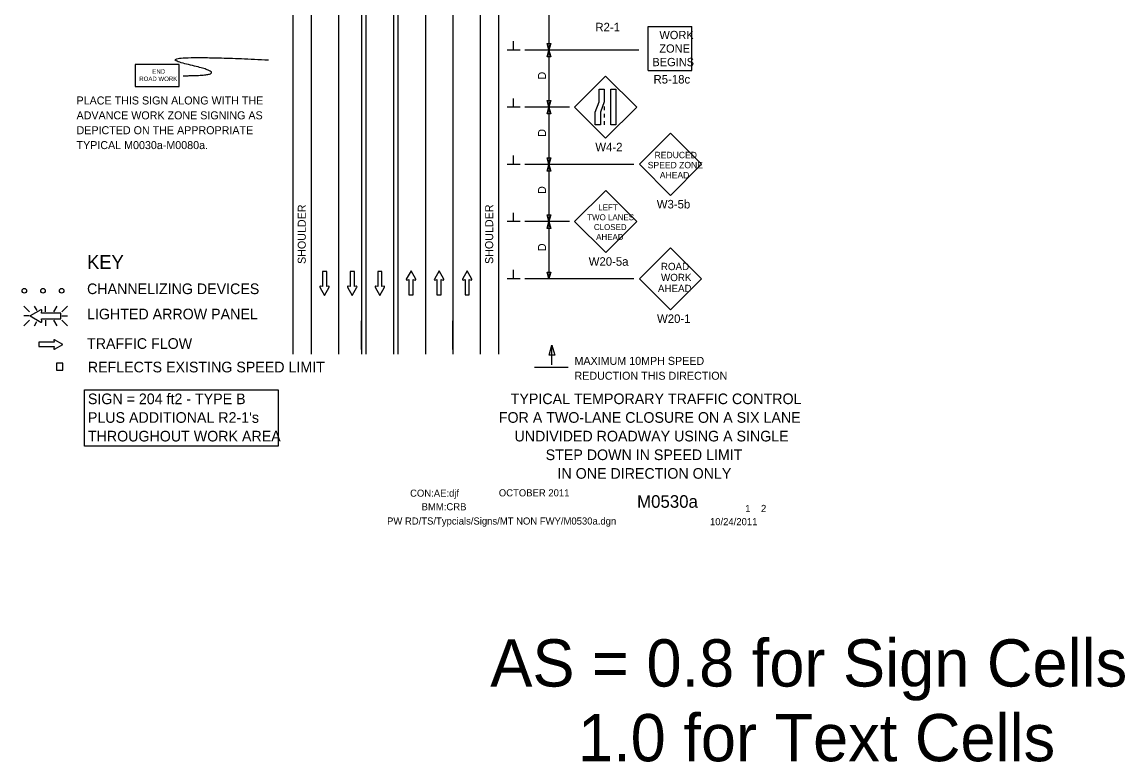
# Model space of a CAD drawing. Extents: x 16751 to 18475, y 5726 to 6923.
# Drawn here: x 16751 to 17716, y 5726 to 6373 of the extents above; entities that cross this region are included whole.
import ezdxf

# ---------------------------------------------------------------- set-up
doc = ezdxf.new("R2010")
doc.units = 0
for name, color, linetype in [('ALI_LEGAL_EX', 7, 'Continuous'), ('BORDER', 7, 'Continuous'), ('BORDER_SIGNAL_WO', 7, 'Continuous'), ('MT_SCRATCH_LEVEL_E', 7, 'Continuous'), ('PAVT_EDGE_EX', 7, 'Continuous'), ('TRAFFIC_SIGNS_PR', 7, 'Continuous'), ('TYPICAL_TEXT_DIMEN_EX', 7, 'Continuous'), ('TYPICAL_TEXT_DIMEN_PR', 7, 'Continuous')]:
    doc.layers.add(name, color=color, linetype=linetype)

msp = doc.modelspace()

# ---------------------------------------------------------------- linework, layer by layer
at = {"layer": 'ALI_LEGAL_EX'}
for p, q in [((17028.08, 6911.72), (17028.08, 6082.53)), ((17048.08, 6911.72), (17048.08, 6082.53)), ((17052.08, 6911.72), (17052.08, 6082.53)), ((17104.08, 6911.72), (17104.08, 6082.53)), ((17128.08, 6911.72), (17128.08, 6082.53)), ((17128.08, 6911.72), (17128.08, 6082.53))]:
    msp.add_line(p, q, dxfattribs=at)
for points in [[(17028.08, 6311.72), (17028.08, 6286.72)], [(17052.08, 6311.72), (17052.08, 6286.72)], [(17104.08, 6311.72), (17104.08, 6286.72)], [(17128.08, 6311.72), (17128.08, 6286.72)], [(17028.08, 6211.72), (17028.08, 6186.72)], [(17052.08, 6211.72), (17052.08, 6186.72)], [(17104.08, 6211.72), (17104.08, 6186.72)], [(17128.08, 6211.72), (17128.08, 6186.72)], [(17028.08, 6111.72), (17028.08, 6086.72)], [(17048.08, 6086.72), (17048.08, 6111.72)], [(17052.08, 6111.72), (17052.08, 6086.72)], [(17104.08, 6111.72), (17104.08, 6086.72)], [(17128.08, 6086.72), (17128.08, 6111.72)], [(17128.08, 6111.72), (17128.08, 6086.72)]]:
    msp.add_lwpolyline(points, dxfattribs=at)
at = {"layer": 'MT_SCRATCH_LEVEL_E'}
for p, q in [((17017.74, 6154.9), (17014, 6154.9)), ((17014, 6154.9), (17014, 6141.64)), ((17017.74, 6154.9), (17014, 6154.9)), ((17014, 6154.9), (17014, 6141.64)), ((17017.74, 6141.64), (17017.74, 6154.9)), ((17017.74, 6141.64), (17017.74, 6154.9)), ((17042, 6154.9), (17038.26, 6154.9)), ((17038.26, 6154.9), (17038.26, 6141.64)), ((17042, 6154.9), (17038.26, 6154.9)), ((17038.26, 6154.9), (17038.26, 6141.64)), ((17042, 6141.64), (17042, 6154.9)), ((17042, 6141.64), (17042, 6154.9)), ((17066.1, 6154.9), (17062.36, 6154.9)), ((17062.36, 6154.9), (17062.36, 6141.64)), ((17066.1, 6154.9), (17062.36, 6154.9)), ((17062.36, 6154.9), (17062.36, 6141.64)), ((17066.1, 6141.64), (17066.1, 6154.9)), ((17066.1, 6141.64), (17066.1, 6154.9)), ((17091.51, 6155.36), (17087.4, 6148.12)), ((17091.51, 6155.36), (17087.4, 6148.12)), ((17095.66, 6148.12), (17091.51, 6155.36)), ((17095.66, 6148.12), (17091.51, 6155.36)), ((17116.04, 6155.36), (17111.93, 6148.12)), ((17116.04, 6155.36), (17111.93, 6148.12)), ((17120.19, 6148.12), (17116.04, 6155.36)), ((17120.19, 6148.12), (17116.04, 6155.36)), ((17140.6, 6155.36), (17136.49, 6148.12)), ((17140.6, 6155.36), (17136.49, 6148.12)), ((17144.75, 6148.12), (17140.6, 6155.36)), ((17144.75, 6148.12), (17140.6, 6155.36)), ((17087.89, 6147.43), (17089.66, 6147.75)), ((17087.89, 6147.43), (17089.66, 6147.75)), ((17089.66, 6147.75), (17089.66, 6134.49)), ((17089.66, 6147.75), (17089.66, 6134.49)), ((17093.4, 6134.49), (17093.4, 6147.75)), ((17093.4, 6147.75), (17095.18, 6147.43)), ((17093.4, 6134.49), (17093.4, 6147.75)), ((17093.4, 6147.75), (17095.18, 6147.43)), ((17112.41, 6147.43), (17114.19, 6147.75)), ((17112.41, 6147.43), (17114.19, 6147.75)), ((17114.19, 6147.75), (17114.19, 6134.49)), ((17114.19, 6147.75), (17114.19, 6134.49)), ((17117.93, 6134.49), (17117.93, 6147.75)), ((17117.93, 6147.75), (17119.71, 6147.43)), ((17117.93, 6134.49), (17117.93, 6147.75)), ((17117.93, 6147.75), (17119.71, 6147.43)), ((17136.97, 6147.43), (17138.75, 6147.75)), ((17136.97, 6147.43), (17138.75, 6147.75)), ((17138.75, 6147.75), (17138.75, 6134.49)), ((17138.75, 6147.75), (17138.75, 6134.49)), ((17142.49, 6134.49), (17142.49, 6147.75)), ((17142.49, 6147.75), (17144.27, 6147.43)), ((17142.49, 6134.49), (17142.49, 6147.75)), ((17142.49, 6147.75), (17144.27, 6147.43)), ((17011.75, 6141.27), (17015.89, 6134.03)), ((17011.75, 6141.27), (17015.89, 6134.03)), ((17014, 6141.64), (17012.23, 6141.96)), ((17014, 6141.64), (17012.23, 6141.96)), ((17015.89, 6134.03), (17020, 6141.27)), ((17015.89, 6134.03), (17020, 6141.27)), ((17019.52, 6141.96), (17017.74, 6141.64)), ((17019.52, 6141.96), (17017.74, 6141.64)), ((17036, 6141.27), (17040.15, 6134.03)), ((17036, 6141.27), (17040.15, 6134.03)), ((17038.26, 6141.64), (17036.48, 6141.96)), ((17038.26, 6141.64), (17036.48, 6141.96)), ((17040.15, 6134.03), (17044.26, 6141.27)), ((17040.15, 6134.03), (17044.26, 6141.27)), ((17043.78, 6141.96), (17042, 6141.64)), ((17043.78, 6141.96), (17042, 6141.64)), ((17060.1, 6141.27), (17064.25, 6134.03)), ((17060.1, 6141.27), (17064.25, 6134.03)), ((17062.36, 6141.64), (17060.58, 6141.96)), ((17062.36, 6141.64), (17060.58, 6141.96)), ((17064.25, 6134.03), (17068.36, 6141.27)), ((17064.25, 6134.03), (17068.36, 6141.27)), ((17067.88, 6141.96), (17066.1, 6141.64)), ((17067.88, 6141.96), (17066.1, 6141.64)), ((17089.66, 6134.49), (17093.4, 6134.49)), ((17089.66, 6134.49), (17093.4, 6134.49)), ((17114.19, 6134.49), (17117.93, 6134.49)), ((17114.19, 6134.49), (17117.93, 6134.49)), ((17138.75, 6134.49), (17142.49, 6134.49)), ((17138.75, 6134.49), (17142.49, 6134.49)), ((16779.38, 6092.98), (16766.12, 6092.98)), ((16766.12, 6092.98), (16766.12, 6089.24)), ((16779.38, 6092.98), (16766.12, 6092.98)), ((16766.12, 6092.98), (16766.12, 6089.24)), ((16766.12, 6089.24), (16779.38, 6089.24)), ((16766.12, 6089.24), (16779.38, 6089.24)), ((16779.06, 6094.76), (16779.38, 6092.98)), ((16779.06, 6094.76), (16779.38, 6092.98)), ((16779.38, 6089.24), (16779.06, 6087.47)), ((16779.38, 6089.24), (16779.06, 6087.47)), ((16786.99, 6091.13), (16779.74, 6095.24)), ((16786.99, 6091.13), (16779.74, 6095.24)), ((16779.74, 6086.99), (16786.99, 6091.13)), ((16779.74, 6086.99), (16786.99, 6091.13))]:
    msp.add_line(p, q, dxfattribs=at)
for centre, start, end in [((17087.81, 6147.89), 150.42484, 279.96381), ((17087.81, 6147.89), 150.42484, 279.96381), ((17095.25, 6147.89), 260.03619, 29.77312), ((17095.25, 6147.89), 260.03619, 29.77312), ((17112.34, 6147.89), 150.42484, 279.96381), ((17112.34, 6147.89), 150.42484, 279.96381), ((17119.78, 6147.89), 260.03619, 29.77312), ((17119.78, 6147.89), 260.03619, 29.77312), ((17136.9, 6147.89), 150.42484, 279.96381), ((17136.9, 6147.89), 150.42484, 279.96381), ((17144.34, 6147.89), 260.03619, 29.77312), ((17144.34, 6147.89), 260.03619, 29.77312), ((17012.16, 6141.5), 80.03619, 209.77312), ((17012.16, 6141.5), 80.03619, 209.77312), ((17019.6, 6141.5), 330.42484, 99.96381), ((17019.6, 6141.5), 330.42484, 99.96381), ((17036.41, 6141.5), 80.03619, 209.77312), ((17036.41, 6141.5), 80.03619, 209.77312), ((17043.85, 6141.5), 330.42484, 99.96381), ((17043.85, 6141.5), 330.42484, 99.96381), ((17060.51, 6141.5), 80.03619, 209.77312), ((17060.51, 6141.5), 80.03619, 209.77312), ((17067.96, 6141.5), 330.42484, 99.96381), ((17067.96, 6141.5), 330.42484, 99.96381), ((16779.52, 6094.84), 60.42484, 189.96381), ((16779.52, 6094.84), 60.42484, 189.96381), ((16779.52, 6087.4), 170.03619, 299.77312), ((16779.52, 6087.4), 170.03619, 299.77312)]:
    msp.add_arc(centre, 0.463, start, end, dxfattribs=at)
at = {"layer": 'PAVT_EDGE_EX'}
for p, q in [((16988.08, 6911.72), (16988.08, 6082.53)), ((17004.08, 6911.72), (17004.08, 6082.53)), ((17076.08, 6911.72), (17076.08, 6082.53)), ((17080.08, 6911.72), (17080.08, 6082.53)), ((17152.08, 6911.72), (17152.08, 6082.53)), ((17168.08, 6911.72), (17168.08, 6082.53))]:
    msp.add_line(p, q, dxfattribs=at)
at = {"layer": 'TRAFFIC_SIGNS_PR'}
for p, q in [((17298.75, 6330.61), (17298.75, 6369.01)), ((17298.75, 6369.01), (17337.15, 6369.01)), ((17337.15, 6330.61), (17337.15, 6369.01)), ((17298.75, 6330.61), (17337.15, 6330.61)), ((17261.72, 6325.68), (17234.57, 6298.53)), ((17288.87, 6298.53), (17261.72, 6325.68)), ((17234.57, 6298.53), (17261.72, 6271.38)), ((17260.47, 6299.02), (17260.47, 6295.82)), ((17261.72, 6271.38), (17288.87, 6298.53)), ((17260.47, 6292.62), (17260.47, 6289.42)), ((17260.47, 6286.22), (17260.47, 6283.02)), ((17318.46, 6275.75), (17291.3, 6248.59)), ((17345.61, 6248.59), (17318.46, 6275.75)), ((17291.3, 6248.59), (17318.46, 6221.44)), ((17318.46, 6221.44), (17345.61, 6248.59)), ((17261.73, 6225.66), (17234.58, 6198.51)), ((17288.88, 6198.51), (17261.73, 6225.66)), ((17234.58, 6198.51), (17261.73, 6171.36)), ((17261.73, 6171.36), (17288.88, 6198.51)), ((17318.46, 6175.69), (17291.31, 6148.54)), ((17345.61, 6148.54), (17318.46, 6175.69)), ((17291.31, 6148.54), (17318.46, 6121.39)), ((17318.46, 6121.39), (17345.61, 6148.54)), ((16752.8, 6124.52), (16757.73, 6119.59)), ((16764.56, 6120.7), (16762.35, 6124.52)), ((16771.88, 6119.59), (16771.88, 6124.52)), ((16779.12, 6119.59), (16781.96, 6124.52)), ((16786.03, 6119.59), (16790.97, 6124.52)), ((16757.73, 6116.03), (16752.8, 6116.03)), ((16786.03, 6116.03), (16790.97, 6116.03)), ((16752.8, 6107.54), (16757.73, 6112.47)), ((16762.31, 6107.54), (16764.42, 6111.2)), ((16771.88, 6112.47), (16771.88, 6107.54)), ((16782.01, 6107.54), (16779.16, 6112.47)), ((16786.03, 6112.47), (16790.97, 6107.54))]:
    msp.add_line(p, q, dxfattribs=at)
for points in [[(16850.28, 6316.64), (16888.68, 6316.64), (16888.68, 6335.84), (16850.28, 6335.84)], [(17260.47, 6314.27), (17260.47, 6303.09), (17257.13, 6294.2), (17257.13, 6283.02), (17252.63, 6283.02), (17252.63, 6294.2), (17255.98, 6303.09), (17255.98, 6314.27)], [(17270.61, 6314.27), (17270.61, 6283.02), (17266.12, 6283.02), (17266.12, 6314.27)], [(16781.55, 6068.55), (16787.14, 6068.55), (16787.14, 6074.73), (16781.55, 6074.73)]]:
    msp.add_lwpolyline(points, close=True, dxfattribs=at)
for points in [[(16767.81, 6121.31), (16758.52, 6116.03), (16767.81, 6110.71)], [(16768.68, 6111.34), (16768.28, 6113.6), (16785.3, 6113.6), (16785.3, 6118.4), (16768.28, 6118.4), (16768.69, 6120.69)]]:
    msp.add_lwpolyline(points, dxfattribs=at)
for centre in [(16753.36, 6138.06), (16769.66, 6138.06), (16785.96, 6138.06)]:
    msp.add_circle(centre, 2, dxfattribs=at)
for centre, radius, start, end in [((16768.1, 6120.78), 0.598, 350.73078, 118.89165), ((16768.09, 6111.23), 0.597, 241.48329, 9.95933)]:
    msp.add_arc(centre, radius, start, end, dxfattribs=at)
msp.add_open_spline([(16892.27, 6326.02), (16939.51, 6326.02), (16854.48, 6345.37), (16966.78, 6339.88)], degree=2, dxfattribs=at)
at = {"layer": 'TYPICAL_TEXT_DIMEN_EX'}
msp.add_lwpolyline([(16805.94, 6051.34), (16975.39, 6051.34), (16975.39, 6002.14), (16805.94, 6002.14)], close=True, dxfattribs=at)
at = {"layer": 'TYPICAL_TEXT_DIMEN_PR'}
for p, q in [((17212.08, 6398.45), (17212.08, 6348.45)), ((17181.2, 6348.45), (17181.2, 6356.23)), ((17186.83, 6348.45), (17175.58, 6348.45)), ((17290.63, 6348.45), (17191.08, 6348.45)), ((17212.08, 6348.45), (17210.51, 6354.31)), ((17210.51, 6354.31), (17212.08, 6354.31)), ((17210.51, 6342.59), (17212.08, 6348.45)), ((17212.08, 6354.31), (17213.65, 6354.31)), ((17213.65, 6354.31), (17212.08, 6348.45)), ((17212.08, 6348.45), (17213.65, 6342.59)), ((17212.08, 6348.45), (17212.08, 6298.45)), ((17212.08, 6342.59), (17210.51, 6342.59)), ((17213.65, 6342.59), (17212.08, 6342.59)), ((17186.83, 6298.45), (17175.58, 6298.45)), ((17181.2, 6298.45), (17181.2, 6306.23)), ((17230.08, 6298.45), (17191.08, 6298.45)), ((17212.08, 6298.45), (17210.51, 6304.31)), ((17210.51, 6304.31), (17212.08, 6304.31)), ((17210.51, 6292.59), (17212.08, 6298.45)), ((17212.08, 6304.31), (17213.65, 6304.31)), ((17213.65, 6304.31), (17212.08, 6298.45)), ((17212.08, 6298.45), (17212.08, 6248.45)), ((17212.08, 6298.45), (17213.65, 6292.59)), ((17212.08, 6292.59), (17210.51, 6292.59)), ((17213.65, 6292.59), (17212.08, 6292.59)), ((17181.2, 6248.45), (17181.2, 6256.23)), ((17212.08, 6248.45), (17210.51, 6254.31)), ((17210.51, 6254.31), (17212.08, 6254.31)), ((17212.08, 6254.31), (17213.65, 6254.31)), ((17213.65, 6254.31), (17212.08, 6248.45)), ((17186.83, 6248.45), (17175.58, 6248.45)), ((17286.28, 6248.45), (17191.08, 6248.45)), ((17210.51, 6242.59), (17212.08, 6248.45)), ((17212.08, 6242.59), (17210.51, 6242.59)), ((17212.08, 6248.45), (17212.08, 6198.45)), ((17212.08, 6248.45), (17213.65, 6242.59)), ((17213.65, 6242.59), (17212.08, 6242.59)), ((17181.2, 6198.45), (17181.2, 6206.23)), ((17212.08, 6198.45), (17210.51, 6204.31)), ((17210.51, 6204.31), (17212.08, 6204.31)), ((17212.08, 6204.31), (17213.65, 6204.31)), ((17213.65, 6204.31), (17212.08, 6198.45)), ((17186.83, 6198.45), (17175.58, 6198.45)), ((17230.08, 6198.45), (17191.08, 6198.45)), ((17210.51, 6192.59), (17212.08, 6198.45)), ((17212.08, 6192.59), (17210.51, 6192.59)), ((17212.08, 6198.45), (17212.08, 6148.45)), ((17212.08, 6198.45), (17213.65, 6192.59)), ((17213.65, 6192.59), (17212.08, 6192.59)), ((17181.2, 6148.45), (17181.2, 6156.23)), ((17212.08, 6148.45), (17210.51, 6154.31)), ((17210.51, 6154.31), (17212.08, 6154.31)), ((17212.08, 6154.31), (17213.65, 6154.31)), ((17213.65, 6154.31), (17212.08, 6148.45)), ((17186.83, 6148.45), (17175.58, 6148.45)), ((17286.28, 6148.45), (17191.08, 6148.45)), ((17212.42, 6081.69), (17214.78, 6090.49)), ((17214.78, 6073.36), (17214.78, 6090.49)), ((17214.78, 6090.49), (17217.13, 6081.69)), ((17214.78, 6081.69), (17212.42, 6081.69)), ((17217.13, 6081.69), (17214.78, 6081.69)), ((17228.95, 6070.86), (17199.51, 6070.86))]:
    msp.add_line(p, q, dxfattribs=at)

# ---------------------------------------------------------------- texts
at = {"layer": 'BORDER'}
for s, p in [('TYPICAL TEMPORARY TRAFFIC CONTROL', (17178.7, 6038.95)), ('FOR A TWO-LANE CLOSURE ON A SIX LANE', (17168.28, 6022.65)), ('UNDIVIDED ROADWAY USING A SINGLE', (17181.98, 6006.35)), ('STEP DOWN IN SPEED LIMIT', (17209.26, 5990.05)), ('IN ONE DIRECTION ONLY', (17219.61, 5973.75))]:
    msp.add_text(s, height=9.3, dxfattribs=at).set_placement(p)
at = {"layer": 'BORDER_SIGNAL_WO'}
for s, height, p in [('CON:AE:djf', 6.2, (17090.69, 5958.06)), ('    OCTOBER 2011    ', 6.2, (17159.08, 5958.34)), ('BMM:CRB   ', 6.2, (17100.81, 5946.17)), ('    M0530a   ', 11, (17272.86, 5948.38)), (' 1    2 ', 6.2, (17381.45, 5944.7)), ('PW RD/TS/Typcials/Signs/MT NON FWY/M0530a.dgn    ', 6.2, (17070.55, 5933.71)), ('10/24/2011    ', 6.2, (17352.93, 5933.13)), ('AS = 0.8 for Sign Cells', 41.2877, (17160.83, 5792.11)), ('     1.0 for Text Cells', 41.2877, (17160.83, 5726.82))]:
    msp.add_text(s, height=height, dxfattribs=at).set_placement(p)
at = {"layer": 'TRAFFIC_SIGNS_PR'}
for s, height, p in [('R2-1', 7.44, (17252.7, 6364.81)), ('WORK', 7.217, (17308.74, 6357.97)), ('ZONE', 7.217, (17308.63, 6346.16)), ('BEGINS', 7.217, (17302.55, 6334.35)), ('END', 3.831, (16865.28, 6327.78)), ('ROAD WORK', 3.831, (16853.89, 6321.39)), ('R5-18c', 7.44, (17303.56, 6319.17)), ('PLACE THIS SIGN ALONG WITH THE', 7, (16799, 6300.87)), ('ADVANCE WORK ZONE SIGNING AS', 7, (16799, 6287.87)), ('DEPICTED ON THE APPROPRIATE', 7, (16799, 6274.87)), ('TYPICAL M0030a-M0080a.', 7, (16799, 6261.87)), ('W4-2', 7.44, (17252.68, 6259.94)), ('REDUCED', 5.6, (17304.51, 6253.9)), ('SPEED ZONE', 5.6, (17298.51, 6245.1)), ('AHEAD', 5.6, (17309.07, 6236.3)), ('LEFT', 5.2, (17255.27, 6208.3)), ('W3-5b', 7.44, (17306.41, 6210)), ('TWO LANES', 5.2, (17245.59, 6199.7)), ('CLOSED', 5.2, (17251.44, 6191.1)), ('AHEAD', 5.2, (17253.39, 6182.5)), ('W20-5a', 7.44, (17246.87, 6159.91)), ('ROAD', 6.4, (17310, 6156.07)), ('WORK', 6.4, (17310.11, 6146.48)), ('AHEAD', 6.4, (17307.42, 6136.88)), ('W20-1', 7.44, (17306.63, 6109.95))]:
    msp.add_text(s, height=height, dxfattribs=at).set_placement(p)
at = {"layer": 'TYPICAL_TEXT_DIMEN_EX'}
for s, height, p in [('KEY', 12, (16808.2, 6157.17)), ('CHANNELIZING DEVICES', 9.3, (16808.2, 6135.12)), ('LIGHTED ARROW PANEL', 9.3, (16808.2, 6113.07)), ('TRAFFIC FLOW', 9.3, (16808.2, 6087.27)), ('REFLECTS EXISTING SPEED LIMIT', 9.3, (16808.84, 6066.72)), ('SIGN = 204 ft2 - TYPE B', 9.3, (16808.95, 6038.93)), ("PLUS ADDITIONAL R2-1's", 9.3, (16808.95, 6022.63)), ('THROUGHOUT WORK AREA', 9.3, (16808.95, 6006.33))]:
    msp.add_text(s, height=height, dxfattribs=at).set_placement(p)
at = {"layer": 'TYPICAL_TEXT_DIMEN_PR'}
for s, p in [('D', (17209.52, 6322.67)), ('D', (17209.52, 6272.67)), ('D', (17209.52, 6222.67)), ('SHOULDER', (16999.45, 6161.47)), ('SHOULDER', (17163.35, 6161.47)), ('D', (17209.52, 6172.67))]:
    msp.add_text(s, height=7, rotation=90, dxfattribs=at).set_placement(p)
for s, p in [('MAXIMUM 10MPH SPEED', (17234.47, 6073.28)), ('REDUCTION THIS DIRECTION', (17234.47, 6060.28))]:
    msp.add_text(s, height=7, dxfattribs=at).set_placement(p)

doc.saveas('drawing.dxf')
